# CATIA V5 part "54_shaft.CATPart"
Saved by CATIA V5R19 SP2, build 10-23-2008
Part number: 54_shaft
Bounding box of the stored display mesh (mm): x -7.637 to 7.637, y 132.725 to 147.999, z 135.948 to 211.448
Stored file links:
  C:\Documents and Settings\anizard\Bureau\13\54_shaft.CATPart
  C:\Program Files (x86)\Dassault Systemes\B19\intel_a\reffiles\standard\MetricThickPitch.txt
  C:\Documents and Settings\anizard\Bureau\13\anizard.CATProduct
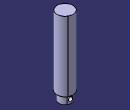
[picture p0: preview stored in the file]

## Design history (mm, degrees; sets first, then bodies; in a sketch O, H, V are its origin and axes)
Set1
  Line1: linked copy from another document
  Point1: linked copy from another document
  Point2: linked copy from another document
  Plane1: linked copy from another document
  Plane2: linked copy from another document
Body1 (main body)
  Sketch1 on yz-plane, origin (0, 0, 0), H (0, 1, 0), V (0, 0, 1)
    line L1 (148.0089, 211.4478) -> (148.0089, 143.9478)
    line L2 (148.0089, 143.9478) -> (146.1119, 143.9478)
    line L3 (146.1119, 143.9478) -> (146.1119, 135.9478)
    line L4 (146.1119, 135.9478) -> (140.3619, 135.9478)
    point P5 (140.3619, 135.9478)
    line L5 (140.3619, 135.9478) -> (140.3619, 211.4478)
    reference projected line E1 (140.3619, -190) -> (140.3619, 190) from Line1
    line L6 (140.3619, 211.4478) -> (148.0089, 211.4478)
    reference intersected line E2 through (0, 143.9478) direction (-1, 0) from Plane1
    reference intersected line E3 through (0, 131.4478) direction (-1, 0) from Plane2
    distance L4 L2 = 8
    distance L3 L5 = 5.75
    distance L1 L5 = 7.647
    distance E3 L6 = 80
    vertical: L1 V, L3 V, L5 V
    horizontal: L2 H, L4 H
    coincidence: P5 E1, L2 E2
  Shaft1: profile Sketch1, axis Sketch1.L5, angle 360
  Plane3: type OffsetPt, RefPlane zx-plane, RefPoint Point1
  Sketch2 on Plane3, origin (0, 140.3619, 0), H (-1, 0, 0), V (0, 0, 1)
    circle A1 centre (0, 139.6978) radius 2
    point P1 (0, 139.6978)
    reference projected point E1 (0, 139.6978) from Point2
    radius A1 = 2
    coincidence: P1 V, P1 E1
  Pocket1: profile Sketch2, direction (0, -1, 0), length 20, mirrored extent
  Thread1: diameter 15.294, depth 67.5, pitch 0.25, on face of Shaft1 from Sketch1.L1, from face of Shaft1 from Sketch1.L2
